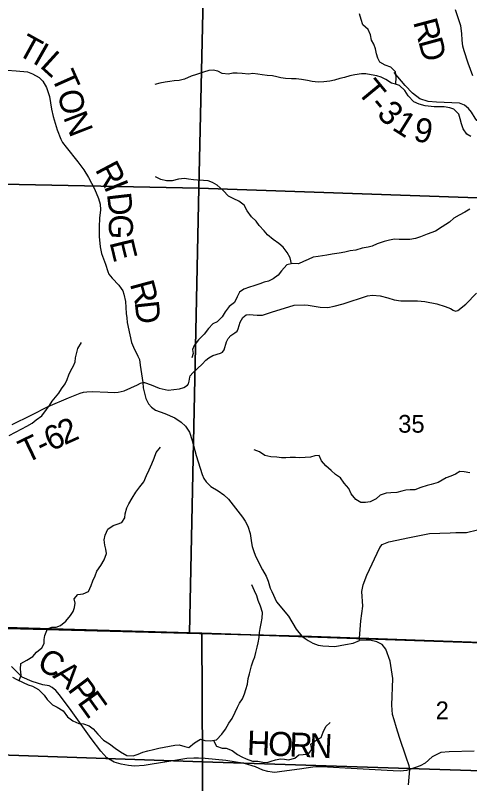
# Model space of a CAD drawing. Extents: x 2043100 to 2470832, y 443715 to 810583.
# Drawn here: x 2244735 to 2250396, y 604826 to 614395 of the extents above; entities that cross this region are included whole.
import ezdxf

# ---------------------------------------------------------------- set-up
doc = ezdxf.new("R2010")
doc.units = 0
for name, color, linetype in [('GM_X_County_Road', 7, 'Continuous'), ('GM_X_County_Road_Text', 7, 'Continuous'), ('GM_X_Minor_River', 7, 'Continuous'), ('GM_X_Section', 7, 'Continuous'), ('GM_X_Section_Text', 7, 'Continuous'), ('GM_X_Township', 7, 'Continuous'), ('GM_X_Township_Road', 7, 'Continuous'), ('GM_X_Township_Road_Text', 7, 'Continuous')]:
    doc.layers.add(name, color=color, linetype=linetype)

msp = doc.modelspace()

# ---------------------------------------------------------------- linework, layer by layer
at = {"layer": 'GM_X_County_Road'}
for points in [[(2249651.1, 605002.8), (2249642.5, 605046.8), (2249604.9, 605156.4), (2249521.4, 605399.6), (2249483.6, 605521.2), (2249454.2, 605621), (2249433.2, 605686.8), (2249427.6, 605802.9), (2249441.2, 606137.2), (2249405.9, 606350.4), (2249353.1, 606500.2), (2249307.3, 606558.3), (2249240.3, 606593.5), (2249150.5, 606612.9), (2249023.6, 606607.6)], [(2249651.1, 605002.8), (2249611.3, 604988.2), (2249533.4, 604979.1), (2249443.3, 604983.8), (2248996.6, 605009.4), (2248551.9, 605033), (2248495.8, 605036.2), (2248443.9, 605031.4), (2248278.1, 605007), (2248056.4, 604977.7), (2247968.4, 604966.4), (2247934.4, 604967.9), (2247880.3, 604975.1), (2247819.9, 604994.3), (2247729.3, 605035.1), (2247590.6, 605075.1), (2247359.9, 605115.8), (2247099.3, 605140.1), (2247019.2, 605144.9), (2246957.2, 605144), (2246873.2, 605136.8), (2246621.6, 605097.1), (2246439.9, 605066.4), (2246340.1, 605051), (2246220.1, 605043.2), (2246145.9, 605050.1), (2246055.6, 605068.9), (2245967.2, 605093.6), (2245874.3, 605148.4), (2245799.1, 605231.4), (2245680.8, 605388), (2245431.7, 605734.9), (2245286.7, 605933.1), (2245238, 605984.5), (2245193.4, 606024), (2245155.1, 606043.4), (2245076.8, 606058.3), (2244944.1, 606098.5), (2244819.3, 606150.7), (2244689.1, 606286.7)], [(2250450.7, 605231.9), (2250142.8, 605220.3), (2250036.8, 605211.7), (2249931.1, 605159.1), (2249841.5, 605080.6), (2249777.7, 605046.2), (2249651.1, 605002.8)], [(2249633.8, 604812.3), (2249651.1, 605002.8)]]:
    msp.add_lwpolyline(points, dxfattribs=at)
at = {"layer": 'GM_X_Minor_River'}
for points in [[(2249476.4, 613537), (2249478.7, 613624.7), (2249474.1, 613690.7), (2249415.6, 613748.3), (2249343.4, 613773.7), (2249277.2, 613811.2), (2249252.7, 613863), (2249236.3, 613916.9), (2249223.7, 613976.9), (2249203.2, 614034.8), (2249174.8, 614086.6), (2249160.2, 614152.6), (2249133.7, 614220.4), (2249067.2, 614277.9), (2249046.6, 614343.8), (2249022, 614413.7)], [(2249952.7, 613254.4), (2249843.6, 613267.4), (2249767.4, 613290.8), (2249699.2, 613318.2), (2249628.6, 613393.7), (2249588.1, 613457.4), (2249521.5, 613522.9), (2249471.4, 613538.5), (2249421.4, 613552.1), (2249351, 613597.5), (2249294.8, 613627.1), (2249238.7, 613642.6), (2249168.6, 613654), (2249104.6, 613667.5), (2249048.6, 613667), (2248966.8, 613656.3), (2248904.9, 613641.7), (2248835.2, 613623.1), (2248779.4, 613606.6), (2248713.6, 613588), (2248653.7, 613577.5), (2248579.9, 613566.8), (2248509.9, 613564.2), (2248431.9, 613571.6), (2248377.8, 613585.1), (2248301.8, 613596.5), (2248233.8, 613605.9), (2248177.8, 613603.4), (2248099.9, 613606.8), (2248043.8, 613618.3), (2247993.8, 613627.9), (2247939.7, 613641.4), (2247871.7, 613646.8), (2247809.7, 613652.3), (2247757.6, 613661.9), (2247693.6, 613671.3), (2247641.7, 613662.9), (2247561.7, 613670.2), (2247499.7, 613675.7), (2247445.8, 613673.2), (2247391.9, 613664.7), (2247311.9, 613672), (2247257.7, 613699.6), (2247201.6, 613711.2), (2247147.7, 613706.7), (2247079.9, 613688.1), (2246992.2, 613657.3), (2246926.5, 613636.7), (2246840.9, 613599.9), (2246777, 613585.3), (2246713.1, 613578.8), (2246661.3, 613570.3), (2246601.4, 613561.8), (2246535.5, 613549.2), (2246473.7, 613532.7)], [(2250412.1, 612885.3), (2250359.7, 612915), (2250315.2, 612980.8), (2250294.7, 613042.8), (2250276.3, 613104.8), (2250261.9, 613162.8), (2250201.3, 613226.5), (2250151.1, 613244.2), (2250078.8, 613257.8), (2249952.7, 613254.4)], [(2248176.5, 611299.9), (2248159.6, 611372.9), (2248123, 611442.6), (2248074.5, 611508.3), (2248020.1, 611551.8), (2247949.7, 611605.3), (2247877.3, 611660.7), (2247836.8, 611712.4), (2247774.3, 611777.9), (2247737.9, 611829.7), (2247677.4, 611885.2), (2247622.8, 611960.8), (2247588.2, 612032.6), (2247519.8, 612080.1), (2247457.6, 612111.6), (2247389.3, 612145), (2247322.8, 612212.5), (2247250.2, 612282), (2247192, 612313.5), (2247135.9, 612333), (2247079.9, 612338.5), (2247005.9, 612343.9), (2246953.9, 612345.5), (2246893.9, 612353), (2246843.8, 612364.5), (2246767.9, 612355.9), (2246690.2, 612335.2), (2246620.3, 612332.6), (2246550.1, 612352), (2246481.9, 612383.4)], [(2250400, 611981.7), (2250336.1, 611945.2), (2250266.1, 611906.7), (2250200.2, 611868.2), (2250144.4, 611819.8), (2250052.6, 611761.1), (2249969.8, 611708.9)], [(2249969.8, 611708.9), (2249865.7, 611669.9), (2249786, 611637.2), (2249720.3, 611614.6), (2249650.5, 611601.9), (2249570.5, 611603.3), (2249516.5, 611604.8), (2249458.5, 611608.3), (2249396.7, 611595.8), (2249330.9, 611579.2), (2249245.2, 611548.4), (2249183.5, 611519.8), (2249129.7, 611509.4), (2249057.8, 611494.7), (2248976.1, 611472), (2248908.3, 611461.4), (2248842.4, 611446.8), (2248770.6, 611434.2), (2248684.8, 611421.4), (2248615, 611406.8), (2248561.1, 611398.3), (2248509.2, 611391.9), (2248445.3, 611381.3), (2248385.6, 611354.8), (2248327.8, 611330.3), (2248264.2, 611299.7), (2248190.2, 611303.1), (2248118.4, 611286.4), (2248051.1, 611213.8), (2248009.6, 611159.4), (2247948.1, 611112.8), (2247890.4, 611084.3), (2247836.5, 611071.8), (2247780.7, 611051.3), (2247709, 611024.6), (2247651.2, 611010.1), (2247581.5, 610983.5), (2247527.8, 610949), (2247500.4, 610888.7), (2247465, 610820.3), (2247399.5, 610767.7), (2247348.2, 610701.2), (2247312.7, 610640.9), (2247251.3, 610576.3), (2247195.6, 610551.8), (2247142.1, 610493.3), (2247086.8, 610424.7), (2247015.5, 610352), (2246964.1, 610283.5), (2246944.6, 610231.3), (2246949.1, 610181.3), (2246933.5, 610131.1)], [(2244659.8, 609162.7), (2244737.4, 609205.4), (2244817, 609244.1), (2244878.6, 609278.7), (2244944.2, 609315.3), (2244995.8, 609357.8), (2245065.3, 609408.4), (2245122.6, 609485), (2245162.1, 609537.3), (2245195.6, 609587.7), (2245237.1, 609640.1), (2245278.7, 609690.5), (2245308.2, 609742.8), (2245355.6, 609805.2), (2245379.1, 609859.5), (2245400.5, 609917.7), (2245428, 609972), (2245459.5, 610028.3), (2245481.1, 610080.6), (2245486.6, 610130.7), (2245496.1, 610180.8), (2245513.6, 610247), (2245560.9, 610321.5)], [(2244784.3, 606108.6), (2244806.1, 606177.6), (2244797.5, 606249.6), (2244802.8, 606323.7), (2244876.4, 606364.3), (2244951.9, 606409), (2244997.4, 606463.5), (2245066.9, 606516.1), (2245092.4, 606570.4), (2245096, 606620.4), (2245103.5, 606672.5), (2245136.7, 606754.9), (2245188.5, 606775.3), (2245244.5, 606775.8), (2245298.3, 606796.3), (2245365.7, 606850.9), (2245423.1, 606919.5), (2245454.6, 606969.8), (2245474.1, 607020), (2245479.7, 607072.1), (2245467.2, 607128), (2245512.7, 607182.5), (2245578.6, 607189), (2245648.2, 607219.7), (2245679.6, 607294), (2245701, 607350.2), (2245730.5, 607414.5), (2245751.9, 607470.8), (2245801.3, 607541.2), (2245840.6, 607613.6), (2245869.9, 607693.9), (2245863.4, 607745.9), (2245849, 607797.8), (2245842.4, 607863.8), (2245853.9, 607920), (2245889.2, 607994.3), (2245952.7, 608040.9), (2246004.6, 608057.4), (2246060.3, 608077.9), (2246099.8, 608136.3), (2246103.3, 608186.3), (2246124.7, 608260.6), (2246150.2, 608312.8), (2246191.6, 608381.3), (2246236.9, 608455.7), (2246286.2, 608522.2), (2246335.6, 608586.7), (2246370.9, 608663), (2246402.3, 608735.4), (2246437.6, 608807.7), (2246466.9, 608878), (2246490.3, 608948.3), (2246543.7, 609014.8)], [(2250004.5, 608578.3), (2249917.2, 608553.5), (2249865.4, 608541.1), (2249787.7, 608514.4), (2249712, 608483.7), (2249656.1, 608483.2), (2249602.1, 608480.8), (2249550.2, 608470.3), (2249490.4, 608453.8), (2249414.5, 608447.1), (2249354.6, 608444.6), (2249280.9, 608419.9), (2249229.4, 608371.5), (2249155.7, 608336.8), (2249099.9, 608326.3), (2249041.9, 608327.8), (2248977.6, 608363.3), (2248921, 608434.8), (2248890.4, 608502.6), (2248831.9, 608568.2), (2248785.4, 608633.8), (2248725, 608675.3), (2248670.6, 608724.9), (2248604.2, 608782.4), (2248549.7, 608846), (2248519.1, 608911.8), (2248465.2, 608907.3), (2248413.4, 608890.8), (2248347.5, 608886.3), (2248281.5, 608885.7), (2248227.5, 608889.2), (2248161.6, 608888.7), (2248107.7, 608882.2), (2248051.7, 608885.7), (2247993.7, 608891.2), (2247919.7, 608894.6), (2247845.6, 608911.9), (2247779.3, 608957.4), (2247709.1, 608982.8)], [(2250397.6, 608696.7), (2250327.3, 608710.3), (2250273.2, 608711.9), (2250219.2, 608679.5), (2250161.3, 608655.1), (2250105.3, 608632.7), (2250004.5, 608578.3)], [(2246455, 605251.1), (2246522.8, 605267.7), (2246588.7, 605278.3), (2246654.5, 605292.9), (2246722.4, 605303.5), (2246778.3, 605308), (2246848.4, 605286.6), (2246898.5, 605277), (2246967.9, 605335.6), (2247043.5, 605380.3), (2247095.6, 605364.8), (2247167.6, 605357.4), (2247241.4, 605370), (2247308.7, 605442.7), (2247354.1, 605503.1), (2247397.4, 605579.5), (2247434.9, 605635.9), (2247476.2, 605714.3), (2247501.6, 605776.6), (2247527.1, 605828.8), (2247564.6, 605881.2), (2247590.1, 605943.4), (2247607.6, 605997.6), (2247629, 606065.9), (2247638.3, 606136), (2247653.8, 606192.2), (2247667.4, 606244.3), (2247676.9, 606294.5), (2247698.3, 606356.7), (2247717.9, 606406.9), (2247731.4, 606459.1), (2247748.8, 606527.2), (2247760.3, 606579.4), (2247771.7, 606647.5), (2247779.2, 606707.7), (2247786.7, 606759.8), (2247798.2, 606819.9), (2247809.5, 606888), (2247812.9, 606956.1), (2247790.3, 607036), (2247759.6, 607107.8), (2247745.1, 607165.7), (2247716.6, 607225.5), (2247680, 607301.2)], [(2244700.4, 606152.7), (2244754.6, 606123.1), (2244830.9, 606085.8), (2244893.1, 606058.3), (2244947.2, 606038.7), (2245023.5, 605999.3), (2245092.1, 605925.9), (2245132.5, 605874.2), (2245197.1, 605808.7), (2245255.3, 605777.2), (2245329.6, 605731.8), (2245384.3, 605656.2), (2245450.7, 605606.7), (2245524.9, 605575.4), (2245582.9, 605571.9), (2245655, 605546.5), (2245705.3, 605508.9), (2245763.9, 605441.3), (2245832.5, 605365.8), (2245906.8, 605320.5), (2245977.2, 605269), (2246045.6, 605221.6), (2246126, 605176.2), (2246201.9, 605170.9), (2246263.7, 605191.4), (2246325.5, 605216), (2246385.3, 605232.5), (2246455, 605251.1)], [(2247206.2, 605364), (2247242.1, 605294), (2247310.3, 605266.5), (2247364.2, 605269), (2247436.4, 605239.6), (2247504.8, 605190.2), (2247559, 605160.6), (2247611.2, 605135), (2247689.4, 605103.7), (2247755.3, 605106.3), (2247817.4, 605094.8), (2247871.4, 605087.2), (2247923.2, 605103.7), (2247975, 605124.2), (2248038.9, 605134.7), (2248090.9, 605129.2), (2248140.9, 605121.6), (2248216.7, 605144.3), (2248268.3, 605182.8), (2248320.2, 605187.2), (2248390.1, 605197.8), (2248429.6, 605252.2), (2248419, 605318.2), (2248482.5, 605366.7), (2248548.1, 605401.3), (2248569.5, 605467.6), (2248602.9, 605535.9), (2248658.4, 605588.4)]]:
    msp.add_lwpolyline(points, dxfattribs=at)
at = {"layer": 'GM_X_Section'}
for points in [[(2247142.3, 617535.9), (2247023.2, 612242.6), (2241726, 612351.6), (2241833.9, 617758.8)], [(2247142.3, 617535.9), (2252461.6, 617374.3), (2252408.2, 612055.5), (2247023.2, 612242.6)], [(2241726, 612351.6), (2247023.2, 612242.6), (2246904.6, 606705.2), (2241747.1, 606853.7), (2241567, 606857.8)], [(2247023.2, 612242.6), (2252408.2, 612055.5), (2252357.3, 606516.7), (2247060.7, 606700.8), (2246904.6, 606705.2)], [(2241747.1, 606853.7), (2246904.6, 606705.2), (2247060.7, 606700.8), (2247067.3, 605097.3), (2241761.4, 605281.2)], [(2247060.7, 606700.8), (2252357.3, 606516.7), (2252340.1, 604925.8), (2247067.3, 605097.3)], [(2241761.4, 605281.2), (2247067.3, 605097.3), (2247072.3, 599804.2), (2241794.9, 599939.5)], [(2247067.3, 605097.3), (2252340.1, 604925.8), (2252374.3, 599634), (2247072.3, 599804.2)]]:
    msp.add_lwpolyline(points, close=True, dxfattribs=at)
at = {"layer": 'GM_X_Township'}
for points in [[(2258081.3, 633732.5), (2257992.6, 628603.2), (2257760.5, 615186.1), (2257653.2, 607589.5), (2257624.6, 606994.4), (2257596.4, 606358.1), (2253890.2, 606463.4), (2249021.7, 606637.8), (2248304.7, 606663.3), (2243521.3, 606786.8), (2239722.4, 606909.9), (2234400.7, 607082.4), (2233675.1, 607105.9), (2233758.1, 612789.2), (2233874.4, 620743.5), (2233877.9, 620982.4), (2233882.7, 621311.5), (2233884.4, 621427.4), (2233890.3, 621836.9), (2233896.9, 622286.3), (2233904.3, 622790.6), (2233907.5, 623014), (2234072.5, 630720.1), (2234171.5, 633589.1)], [(2234400.7, 607082.4), (2239722.4, 606909.9), (2243521.3, 606786.8), (2248304.7, 606663.3), (2249021.7, 606637.8), (2253890.2, 606463.4), (2257596.4, 606358.1), (2257565.4, 605638.9), (2257563.6, 605306.8), (2257562.2, 605061.7), (2257568.4, 604957), (2257564.9, 604475.8), (2257574, 602803.7), (2257579.2, 602655.8), (2257603, 601401.2), (2257611.2, 601163.6), (2257605.5, 595412.8)]]:
    msp.add_lwpolyline(points, dxfattribs=at)
at = {"layer": 'GM_X_Township_Road'}
for points in [[(2250435.7, 613643.5), (2250376.9, 613800.8), (2250328.1, 613954.3), (2250311.1, 614010.1), (2250301.8, 614084.1), (2250300.2, 614170.3), (2250284.5, 614266.3), (2250218.9, 614465.6)], [(2244631.5, 613713.7), (2244745.7, 613705.4), (2244888, 613691.4), (2244950.4, 613668.3), (2245031.1, 613619.3), (2245077.8, 613573.9), (2245124.9, 613496.4), (2245160.5, 613384.7), (2245184.8, 613228.7), (2245206.1, 613134.9), (2245256.5, 612971.3), (2245302.2, 612853.7), (2245320.8, 612811.9), (2245367.7, 612752.4), (2245514.4, 612570.2), (2245587.9, 612469), (2245647.3, 612373.7), (2245723.3, 612234.5), (2245771.1, 612115), (2245792.1, 612045.2), (2245795.1, 611971.1), (2245784.6, 611870.7), (2245780.1, 611762.4), (2245779.8, 611640.2), (2245793.7, 611512.2), (2245806.9, 611430.2), (2245856.8, 611296.7), (2245886.1, 611204.9), (2245900.6, 611173.1), (2245941.3, 611123.6), (2246022.7, 611032.6), (2246055.3, 610993), (2246073.7, 610965.2), (2246088.3, 610923.3), (2246107.6, 610831.4), (2246115.7, 610681.3), (2246122.5, 610629.3), (2246127.3, 610571.2), (2246163.6, 610415.5), (2246180.9, 610321.6), (2246205.8, 610263.8), (2246263.4, 610150.4), (2246282.1, 610106.6), (2246291.1, 610036.6), (2246322.1, 609822.7), (2246329.1, 609756.7), (2246348.3, 609672.8), (2246361, 609620.9), (2246394, 609555.3), (2246430.6, 609515.7), (2246481.1, 609478.4), (2246597.8, 609436), (2246720.7, 609381.7), (2246801.5, 609328.8), (2246854.3, 609277.5), (2246903.4, 609202), (2246938.9, 609100.4), (2246987.6, 608912.8), (2247063, 608677.4), (2247085.7, 608625.7), (2247112.3, 608584), (2247171.2, 608528.8), (2247264, 608474), (2247332.8, 608424.9), (2247389.6, 608369.6), (2247477.2, 608258.7), (2247566.9, 608143.8), (2247599.6, 608096.2), (2247630.6, 608032.6), (2247659.9, 607940.8), (2247679.5, 607826.9), (2247688.2, 607781), (2247702.9, 607729.1), (2247728, 607657.3), (2247814.4, 607490.3), (2247859.6, 607410.8), (2247884.5, 607347.1), (2247911.7, 607261.3), (2247930.4, 607217.5), (2247990.2, 607092.2), (2248140.9, 606910.7), (2248234.3, 606748.6), (2248304.7, 606663.3), (2248336.1, 606642)], [(2250524, 613069.7), (2250487.8, 613086.5), (2250467.1, 613115.4), (2250420.8, 613189.4), (2250382.6, 613235.4), (2250332.4, 613277.3), (2250268.3, 613301.1), (2249984.1, 613314.1), (2249880, 613321.7), (2249775.8, 613357.4), (2249683.5, 613427.2), (2249593.2, 613523.1), (2249454.6, 613685)], [(2244694.4, 609300.3), (2244930.9, 609413.9), (2245145.6, 609521.2), (2245396.2, 609631), (2245543.5, 609689.2), (2245585.3, 609701.8), (2245625.3, 609706.4), (2245693.3, 609709.4), (2245889.5, 609700.2), (2245969.7, 609697.4), (2246015.6, 609700.1), (2246091.4, 609719.2), (2246256.5, 609793.7), (2246295.9, 609813), (2246322.1, 609822.7), (2246345.7, 609822.6), (2246428.6, 609792.2), (2246525.3, 609753.5), (2246639.7, 609727.1), (2246779.6, 609741.2), (2246833.4, 609758), (2246881, 609788.7), (2246894.8, 609805), (2246902.3, 609839.1), (2246907.6, 609889.3), (2246913.4, 609905.4), (2246944.8, 609943.9), (2247061.4, 610049.8), (2247108.8, 610098.6), (2247144.3, 610131.1), (2247198, 610158), (2247293.6, 610189.4), (2247317.5, 610201.8), (2247337.1, 610230.1), (2247365.7, 610328.7), (2247387.1, 610371.1), (2247418.6, 610405.6), (2247470.2, 610440.4), (2247497.9, 610460.8), (2247513.5, 610489.1), (2247536.3, 610571.6), (2247571.5, 610632.2), (2247611.1, 610664.9), (2247649, 610669.4), (2247747.3, 610658.8), (2247815.3, 610661.8), (2247926.8, 610697.5), (2248209.8, 610785.7), (2248333.8, 610791.5), (2248383.9, 610784.3), (2248534.4, 610758.4), (2248628.5, 610757.7), (2248706.3, 610770.9), (2248822, 610802.6), (2249124.8, 610903.2), (2249184.8, 610908.1), (2249280.9, 610901.5), (2249375.3, 610876.8), (2249453.8, 610849.9), (2249538, 610839.1), (2249746.2, 610838.1), (2249836.3, 610829.4), (2249986.8, 610803.5), (2250090.5, 610770.2), (2250158.6, 610742.4), (2250192.7, 610722.4), (2250218.7, 610712.5), (2250248.7, 610718.6), (2250348.5, 610799.2), (2250482.2, 610936.1)], [(2249023.6, 606607.6), (2249021.7, 606637.8), (2249041.2, 606854.3), (2249065.9, 607035.8), (2249053.2, 607219.8), (2249070, 607302.2), (2249116.3, 607421), (2249277.5, 607768), (2249307, 607804.4), (2249390.6, 607837.7), (2249648, 607893.5), (2249897.5, 607943.2), (2250153.6, 607951.5), (2250223.6, 607954.8), (2250305.6, 607954.3), (2250357.6, 607955.3), (2250493, 607987.8)], [(2248336.1, 606642), (2248384.1, 606609.4), (2248440.5, 606575.9), (2248509.2, 606549.5), (2248567.3, 606542.4), (2248717.1, 606533.6), (2248847.4, 606560.1), (2248944.3, 606575.9), (2249023.6, 606607.6)]]:
    msp.add_lwpolyline(points, dxfattribs=at)

# ---------------------------------------------------------------- texts
at = {"layer": 'GM_X_County_Road_Text'}
for s, rotation, p in [('C', 331.11978, (2244987.5, 606268.2)), ('A', 319.35999, (2245189.9, 606158.4)), ('P', 306.8585, (2245378.4, 605999.1)), ('E', 305.72899, (2245498.9, 605838.4)), ('H', 357.719, (2247616.8, 605186.5)), ('O', 357.7219, (2247880.6, 605176)), ('R', 357.6537, (2248144.3, 605165.5)), ('N', 357.20126, (2248389.8, 605155.4))]:
    msp.add_text(s, height=300, rotation=rotation, dxfattribs=at).set_placement(p)
at = {"layer": 'GM_X_Section_Text'}
for s, height, p in [('35', 220.83, (2249506.4, 609197)), ('2', 220.8, (2249972.8, 605628.7))]:
    msp.add_text(s, height=height, rotation=0.00001, dxfattribs=at).set_placement(p)
at = {"layer": 'GM_X_Township_Road_Text'}
for s, rotation, p in [('R', 284.83614, (2249690.4, 614314.1)), ('T', 331.1402, (2244741.2, 613915.3)), ('D', 285.18804, (2249754, 614073.9)), ('I', 330.30547, (2244936.8, 613807.5)), ('L', 317.69806, (2245029.7, 613756.7)), ('T', 294.03429, (2245176.6, 613632.1)), ('T', 309.5795, (2248983.7, 613444.2)), ('O', 280.5955, (2245262.5, 613444.8)), ('-', 310.35552, (2249129.5, 613267.8)), ('3', 315.16817, (2249228, 613153.8)), ('N', 291.23299, (2245327.7, 613126.9)), ('1', 327.96542, (2249416.1, 612978.1)), ('9', 349.10346, (2249684.5, 612836.2)), ('R', 297.87252, (2245723.1, 612476.2)), ('I', 291.96956, (2245834.9, 612265.8)), ('D', 276.57513, (2245875.7, 612172.1)), ('G', 268.15273, (2245905.5, 611921.5)), ('E', 283.79178, (2245906.2, 611569)), ('R', 285.12779, (2246159.8, 611051.6)), ('D', 276.20503, (2246221.8, 610825.9)), ('2', 24.23249, (2245346.8, 609038.7)), ('6', 25.3432, (2245181.1, 608960.3)), ('T', 25.7447, (2244868.5, 608809.7)), ('-', 25.65733, (2245070.5, 608907.1))]:
    msp.add_text(s, height=300, rotation=rotation, dxfattribs=at).set_placement(p)

doc.saveas('drawing.dxf')
